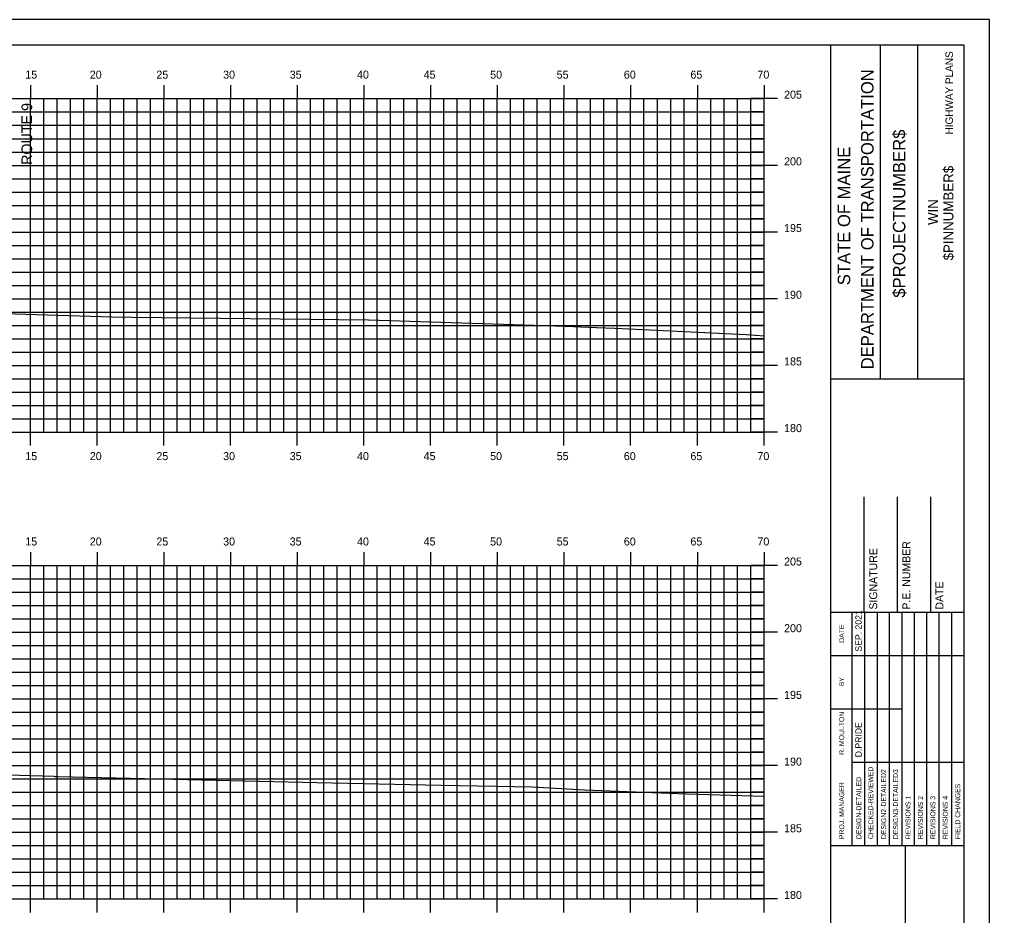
# Model space of a CAD drawing. Extents: x 1723543 to 1723714, y 458501 to 458611.
# Drawn here: x 1723640 to 1723712.7, y 458544 to 458611.2 of the extents above; entities that cross this region are included whole.
import ezdxf

# ---------------------------------------------------------------- set-up
doc = ezdxf.new("R2010")
doc.units = 0
for name, color, linetype in [('ANNOTATION', 7, 'Continuous'), ('BORDER', 7, 'Continuous'), ('H_V ANNOTATION', 7, 'Continuous'), ('HIGHWAY_TITLE', 7, 'Continuous'), ('MAJOR', 7, 'Continuous'), ('MINOR', 7, 'Continuous'), ('PLOT BOUNDARY', 7, 'Continuous'), ('S_Roadway_Centerline', 7, 'Continuous')]:
    doc.layers.add(name, color=color, linetype=linetype)

msp = doc.modelspace()

# ---------------------------------------------------------------- linework, layer by layer
at = {"layer": 'BORDER'}
for p, q in [((1723700.786, 458504.254), (1723700.786, 458609.254)), ((1723704.514, 458584.251), (1723704.514, 458609.251)), ((1723707.309, 458584.251), (1723707.309, 458609.251)), ((1723700.786, 458584.248), (1723710.786, 458584.248)), ((1723703.286, 458566.757), (1723703.286, 458575.405)), ((1723705.786, 458566.757), (1723705.786, 458575.405)), ((1723708.286, 458566.757), (1723708.286, 458575.405)), ((1723700.786, 458566.757), (1723710.786, 458566.757)), ((1723700.786, 458549.257), (1723710.786, 458549.257)), ((1723706.377, 458514.257), (1723706.377, 458549.257))]:
    msp.add_line(p, q, dxfattribs=at)
msp.add_lwpolyline([(1723550.786, 458504.254), (1723710.786, 458504.254), (1723710.786, 458609.254), (1723550.786, 458609.254)], close=True, dxfattribs=at)
for points in [[(1723702.4, 458563.507), (1723702.4, 458566.757)], [(1723703.333, 458549.26), (1723703.333, 458566.757)], [(1723704.265, 458566.757), (1723704.265, 458549.26)], [(1723705.196, 458549.26), (1723705.196, 458566.757)], [(1723706.128, 458549.26), (1723706.128, 458566.757)], [(1723707.06, 458549.26), (1723707.06, 458566.757)], [(1723707.991, 458549.26), (1723707.991, 458566.757)], [(1723708.923, 458549.26), (1723708.923, 458566.757)], [(1723709.855, 458549.26), (1723709.855, 458566.757)], [(1723702.401, 458549.26), (1723702.401, 458566.051)], [(1723700.786, 458563.507), (1723710.786, 458563.507)], [(1723700.786, 458559.507), (1723702.401, 458559.507)], [(1723702.4, 458559.507), (1723706.127, 458559.507)], [(1723702.4, 458555.507), (1723710.786, 458555.507)]]:
    msp.add_lwpolyline(points, dxfattribs=at)
at = {"layer": 'MAJOR'}
for p, q in [((1723640.785, 458606.256), (1723640.785, 458605.254)), ((1723645.785, 458606.256), (1723645.785, 458605.254)), ((1723650.785, 458606.256), (1723650.785, 458605.254)), ((1723655.785, 458606.256), (1723655.785, 458605.254)), ((1723660.785, 458606.256), (1723660.785, 458605.254)), ((1723665.785, 458606.256), (1723665.785, 458605.254)), ((1723670.785, 458606.256), (1723670.785, 458605.254)), ((1723675.785, 458606.256), (1723675.785, 458605.254)), ((1723680.785, 458606.256), (1723680.785, 458605.254)), ((1723685.785, 458606.256), (1723685.785, 458605.254)), ((1723690.785, 458606.256), (1723690.785, 458605.254)), ((1723695.785, 458606.256), (1723695.785, 458605.254)), ((1723555.785, 458605.254), (1723695.785, 458605.254)), ((1723555.785, 458605.254), (1723695.785, 458605.254)), ((1723640.785, 458580.254), (1723640.785, 458605.254)), ((1723645.785, 458580.254), (1723645.785, 458605.254)), ((1723650.785, 458580.254), (1723650.785, 458605.254)), ((1723655.785, 458580.254), (1723655.785, 458605.254)), ((1723660.785, 458580.254), (1723660.785, 458605.254)), ((1723665.785, 458580.254), (1723665.785, 458605.254)), ((1723670.785, 458580.254), (1723670.785, 458605.254)), ((1723675.785, 458580.254), (1723675.785, 458605.254)), ((1723680.785, 458580.254), (1723680.785, 458605.254)), ((1723685.785, 458580.254), (1723685.785, 458605.254)), ((1723690.785, 458580.254), (1723690.785, 458605.254)), ((1723696.787, 458605.254), (1723694.783, 458605.254)), ((1723695.785, 458580.254), (1723695.785, 458605.254)), ((1723695.785, 458580.254), (1723695.785, 458605.254)), ((1723555.785, 458600.254), (1723695.785, 458600.254)), ((1723696.787, 458600.254), (1723694.783, 458600.254)), ((1723555.785, 458595.254), (1723695.785, 458595.254)), ((1723696.787, 458595.254), (1723694.783, 458595.254)), ((1723555.785, 458590.254), (1723695.785, 458590.254)), ((1723696.787, 458590.254), (1723694.783, 458590.254)), ((1723555.785, 458585.254), (1723695.785, 458585.254)), ((1723696.787, 458585.254), (1723694.783, 458585.254)), ((1723555.785, 458580.254), (1723695.785, 458580.254)), ((1723555.785, 458580.254), (1723695.785, 458580.254)), ((1723640.785, 458579.252), (1723640.785, 458580.254)), ((1723645.785, 458579.252), (1723645.785, 458580.254)), ((1723650.785, 458579.252), (1723650.785, 458580.254)), ((1723655.785, 458579.252), (1723655.785, 458580.254)), ((1723660.785, 458579.252), (1723660.785, 458580.254)), ((1723665.785, 458579.252), (1723665.785, 458580.254)), ((1723670.785, 458579.252), (1723670.785, 458580.254)), ((1723675.785, 458579.252), (1723675.785, 458580.254)), ((1723680.785, 458579.252), (1723680.785, 458580.254)), ((1723685.785, 458579.252), (1723685.785, 458580.254)), ((1723690.785, 458579.252), (1723690.785, 458580.254)), ((1723696.787, 458580.254), (1723694.783, 458580.254)), ((1723695.785, 458579.252), (1723695.785, 458580.254)), ((1723640.785, 458571.256), (1723640.785, 458570.254)), ((1723645.785, 458571.256), (1723645.785, 458570.254)), ((1723650.785, 458571.256), (1723650.785, 458570.254)), ((1723655.785, 458571.256), (1723655.785, 458570.254)), ((1723660.785, 458571.256), (1723660.785, 458570.254)), ((1723665.785, 458571.256), (1723665.785, 458570.254)), ((1723670.785, 458571.256), (1723670.785, 458570.254)), ((1723675.785, 458571.256), (1723675.785, 458570.254)), ((1723680.785, 458571.256), (1723680.785, 458570.254)), ((1723685.785, 458571.256), (1723685.785, 458570.254)), ((1723690.785, 458571.256), (1723690.785, 458570.254)), ((1723695.785, 458571.256), (1723695.785, 458570.254)), ((1723555.785, 458570.254), (1723695.785, 458570.254)), ((1723555.785, 458570.254), (1723695.785, 458570.254)), ((1723640.785, 458545.254), (1723640.785, 458570.254)), ((1723645.785, 458545.254), (1723645.785, 458570.254)), ((1723650.785, 458545.254), (1723650.785, 458570.254)), ((1723655.785, 458545.254), (1723655.785, 458570.254)), ((1723660.785, 458545.254), (1723660.785, 458570.254)), ((1723665.785, 458545.254), (1723665.785, 458570.254)), ((1723670.785, 458545.254), (1723670.785, 458570.254)), ((1723675.785, 458545.254), (1723675.785, 458570.254)), ((1723680.785, 458545.254), (1723680.785, 458570.254)), ((1723685.785, 458545.254), (1723685.785, 458570.254)), ((1723690.785, 458545.254), (1723690.785, 458570.254)), ((1723696.787, 458570.254), (1723694.783, 458570.254)), ((1723695.785, 458545.254), (1723695.785, 458570.254)), ((1723695.785, 458545.254), (1723695.785, 458570.254)), ((1723555.785, 458565.254), (1723695.785, 458565.254)), ((1723696.787, 458565.254), (1723694.783, 458565.254)), ((1723555.785, 458560.254), (1723695.785, 458560.254)), ((1723696.787, 458560.254), (1723694.783, 458560.254)), ((1723555.785, 458555.254), (1723695.785, 458555.254)), ((1723696.787, 458555.254), (1723694.783, 458555.254)), ((1723555.785, 458550.254), (1723695.785, 458550.254)), ((1723696.787, 458550.254), (1723694.783, 458550.254)), ((1723555.785, 458545.254), (1723695.785, 458545.254)), ((1723555.785, 458545.254), (1723695.785, 458545.254)), ((1723640.785, 458544.252), (1723640.785, 458545.254)), ((1723645.785, 458544.252), (1723645.785, 458545.254)), ((1723650.785, 458544.252), (1723650.785, 458545.254)), ((1723655.785, 458544.252), (1723655.785, 458545.254)), ((1723660.785, 458544.252), (1723660.785, 458545.254)), ((1723665.785, 458544.252), (1723665.785, 458545.254)), ((1723670.785, 458544.252), (1723670.785, 458545.254)), ((1723675.785, 458544.252), (1723675.785, 458545.254)), ((1723680.785, 458544.252), (1723680.785, 458545.254)), ((1723685.785, 458544.252), (1723685.785, 458545.254)), ((1723690.785, 458544.252), (1723690.785, 458545.254)), ((1723696.787, 458545.254), (1723694.783, 458545.254)), ((1723695.785, 458544.252), (1723695.785, 458545.254))]:
    msp.add_line(p, q, dxfattribs=at)
at = {"layer": 'MINOR'}
for p, q in [((1723641.785, 458580.254), (1723641.785, 458605.254)), ((1723642.785, 458580.254), (1723642.785, 458605.254)), ((1723643.785, 458580.254), (1723643.785, 458605.254)), ((1723644.785, 458580.254), (1723644.785, 458605.254)), ((1723646.785, 458580.254), (1723646.785, 458605.254)), ((1723647.785, 458580.254), (1723647.785, 458605.254)), ((1723648.785, 458580.254), (1723648.785, 458605.254)), ((1723649.785, 458580.254), (1723649.785, 458605.254)), ((1723651.785, 458580.254), (1723651.785, 458605.254)), ((1723652.785, 458580.254), (1723652.785, 458605.254)), ((1723653.785, 458580.254), (1723653.785, 458605.254)), ((1723654.785, 458580.254), (1723654.785, 458605.254)), ((1723656.785, 458580.254), (1723656.785, 458605.254)), ((1723657.785, 458580.254), (1723657.785, 458605.254)), ((1723658.785, 458580.254), (1723658.785, 458605.254)), ((1723659.785, 458580.254), (1723659.785, 458605.254)), ((1723661.785, 458580.254), (1723661.785, 458605.254)), ((1723662.785, 458580.254), (1723662.785, 458605.254)), ((1723663.785, 458580.254), (1723663.785, 458605.254)), ((1723664.785, 458580.254), (1723664.785, 458605.254)), ((1723666.785, 458580.254), (1723666.785, 458605.254)), ((1723667.785, 458580.254), (1723667.785, 458605.254)), ((1723668.785, 458580.254), (1723668.785, 458605.254)), ((1723669.785, 458580.254), (1723669.785, 458605.254)), ((1723671.785, 458580.254), (1723671.785, 458605.254)), ((1723672.785, 458580.254), (1723672.785, 458605.254)), ((1723673.785, 458580.254), (1723673.785, 458605.254)), ((1723674.785, 458580.254), (1723674.785, 458605.254)), ((1723676.785, 458580.254), (1723676.785, 458605.254)), ((1723677.785, 458580.254), (1723677.785, 458605.254)), ((1723678.785, 458580.254), (1723678.785, 458605.254)), ((1723679.785, 458580.254), (1723679.785, 458605.254)), ((1723681.785, 458580.254), (1723681.785, 458605.254)), ((1723682.785, 458580.254), (1723682.785, 458605.254)), ((1723683.785, 458580.254), (1723683.785, 458605.254)), ((1723684.785, 458580.254), (1723684.785, 458605.254)), ((1723686.785, 458580.254), (1723686.785, 458605.254)), ((1723687.785, 458580.254), (1723687.785, 458605.254)), ((1723688.785, 458580.254), (1723688.785, 458605.254)), ((1723689.785, 458580.254), (1723689.785, 458605.254)), ((1723691.785, 458580.254), (1723691.785, 458605.254)), ((1723692.785, 458580.254), (1723692.785, 458605.254)), ((1723693.785, 458580.254), (1723693.785, 458605.254)), ((1723694.785, 458580.254), (1723694.785, 458605.254)), ((1723555.785, 458604.254), (1723695.785, 458604.254)), ((1723695.785, 458604.254), (1723694.783, 458604.254)), ((1723555.785, 458603.254), (1723695.785, 458603.254)), ((1723695.785, 458603.254), (1723694.783, 458603.254)), ((1723555.785, 458602.254), (1723695.785, 458602.254)), ((1723695.785, 458602.254), (1723694.783, 458602.254)), ((1723555.785, 458601.254), (1723695.785, 458601.254)), ((1723695.785, 458601.254), (1723694.783, 458601.254)), ((1723555.785, 458599.254), (1723695.785, 458599.254)), ((1723695.785, 458599.254), (1723694.783, 458599.254)), ((1723555.785, 458598.254), (1723695.785, 458598.254)), ((1723695.785, 458598.254), (1723694.783, 458598.254)), ((1723555.785, 458597.254), (1723695.785, 458597.254)), ((1723695.785, 458597.254), (1723694.783, 458597.254)), ((1723555.785, 458596.254), (1723695.785, 458596.254)), ((1723695.785, 458596.254), (1723694.783, 458596.254)), ((1723555.785, 458594.254), (1723695.785, 458594.254)), ((1723695.785, 458594.254), (1723694.783, 458594.254)), ((1723555.785, 458593.254), (1723695.785, 458593.254)), ((1723695.785, 458593.254), (1723694.783, 458593.254)), ((1723555.785, 458592.254), (1723695.785, 458592.254)), ((1723695.785, 458592.254), (1723694.783, 458592.254)), ((1723555.785, 458591.254), (1723695.785, 458591.254)), ((1723695.785, 458591.254), (1723694.783, 458591.254)), ((1723555.785, 458589.254), (1723695.785, 458589.254)), ((1723695.785, 458589.254), (1723694.783, 458589.254)), ((1723555.785, 458588.254), (1723695.785, 458588.254)), ((1723695.785, 458588.254), (1723694.783, 458588.254)), ((1723555.785, 458587.254), (1723695.785, 458587.254)), ((1723695.785, 458587.254), (1723694.783, 458587.254)), ((1723555.785, 458586.254), (1723695.785, 458586.254)), ((1723695.785, 458586.254), (1723694.783, 458586.254)), ((1723555.785, 458584.254), (1723695.785, 458584.254)), ((1723695.785, 458584.254), (1723694.783, 458584.254)), ((1723555.785, 458583.254), (1723695.785, 458583.254)), ((1723695.785, 458583.254), (1723694.783, 458583.254)), ((1723555.785, 458582.254), (1723695.785, 458582.254)), ((1723695.785, 458582.254), (1723694.783, 458582.254)), ((1723555.785, 458581.254), (1723695.785, 458581.254)), ((1723695.785, 458581.254), (1723694.783, 458581.254)), ((1723641.785, 458545.254), (1723641.785, 458570.254)), ((1723642.785, 458545.254), (1723642.785, 458570.254)), ((1723643.785, 458545.254), (1723643.785, 458570.254)), ((1723644.785, 458545.254), (1723644.785, 458570.254)), ((1723646.785, 458545.254), (1723646.785, 458570.254)), ((1723647.785, 458545.254), (1723647.785, 458570.254)), ((1723648.785, 458545.254), (1723648.785, 458570.254)), ((1723649.785, 458545.254), (1723649.785, 458570.254)), ((1723651.785, 458545.254), (1723651.785, 458570.254)), ((1723652.785, 458545.254), (1723652.785, 458570.254)), ((1723653.785, 458545.254), (1723653.785, 458570.254)), ((1723654.785, 458545.254), (1723654.785, 458570.254)), ((1723656.785, 458545.254), (1723656.785, 458570.254)), ((1723657.785, 458545.254), (1723657.785, 458570.254)), ((1723658.785, 458545.254), (1723658.785, 458570.254)), ((1723659.785, 458545.254), (1723659.785, 458570.254)), ((1723661.785, 458545.254), (1723661.785, 458570.254)), ((1723662.785, 458545.254), (1723662.785, 458570.254)), ((1723663.785, 458545.254), (1723663.785, 458570.254)), ((1723664.785, 458545.254), (1723664.785, 458570.254)), ((1723666.785, 458545.254), (1723666.785, 458570.254)), ((1723667.785, 458545.254), (1723667.785, 458570.254)), ((1723668.785, 458545.254), (1723668.785, 458570.254)), ((1723669.785, 458545.254), (1723669.785, 458570.254)), ((1723671.785, 458545.254), (1723671.785, 458570.254)), ((1723672.785, 458545.254), (1723672.785, 458570.254)), ((1723673.785, 458545.254), (1723673.785, 458570.254)), ((1723674.785, 458545.254), (1723674.785, 458570.254)), ((1723676.785, 458545.254), (1723676.785, 458570.254)), ((1723677.785, 458545.254), (1723677.785, 458570.254)), ((1723678.785, 458545.254), (1723678.785, 458570.254)), ((1723679.785, 458545.254), (1723679.785, 458570.254)), ((1723681.785, 458545.254), (1723681.785, 458570.254)), ((1723682.785, 458545.254), (1723682.785, 458570.254)), ((1723683.785, 458545.254), (1723683.785, 458570.254)), ((1723684.785, 458545.254), (1723684.785, 458570.254)), ((1723686.785, 458545.254), (1723686.785, 458570.254)), ((1723687.785, 458545.254), (1723687.785, 458570.254)), ((1723688.785, 458545.254), (1723688.785, 458570.254)), ((1723689.785, 458545.254), (1723689.785, 458570.254)), ((1723691.785, 458545.254), (1723691.785, 458570.254)), ((1723692.785, 458545.254), (1723692.785, 458570.254)), ((1723693.785, 458545.254), (1723693.785, 458570.254)), ((1723694.785, 458545.254), (1723694.785, 458570.254)), ((1723555.785, 458569.254), (1723695.785, 458569.254)), ((1723695.785, 458569.254), (1723694.783, 458569.254)), ((1723555.785, 458568.254), (1723695.785, 458568.254)), ((1723695.785, 458568.254), (1723694.783, 458568.254)), ((1723555.785, 458567.254), (1723695.785, 458567.254)), ((1723695.785, 458567.254), (1723694.783, 458567.254)), ((1723555.785, 458566.254), (1723695.785, 458566.254)), ((1723695.785, 458566.254), (1723694.783, 458566.254)), ((1723555.785, 458564.254), (1723695.785, 458564.254)), ((1723695.785, 458564.254), (1723694.783, 458564.254)), ((1723555.785, 458563.254), (1723695.785, 458563.254)), ((1723695.785, 458563.254), (1723694.783, 458563.254)), ((1723555.785, 458562.254), (1723695.785, 458562.254)), ((1723695.785, 458562.254), (1723694.783, 458562.254)), ((1723555.785, 458561.254), (1723695.785, 458561.254)), ((1723695.785, 458561.254), (1723694.783, 458561.254)), ((1723555.785, 458559.254), (1723695.785, 458559.254)), ((1723695.785, 458559.254), (1723694.783, 458559.254)), ((1723555.785, 458558.254), (1723695.785, 458558.254)), ((1723695.785, 458558.254), (1723694.783, 458558.254)), ((1723555.785, 458557.254), (1723695.785, 458557.254)), ((1723695.785, 458557.254), (1723694.783, 458557.254)), ((1723555.785, 458556.254), (1723695.785, 458556.254)), ((1723695.785, 458556.254), (1723694.783, 458556.254)), ((1723555.785, 458554.254), (1723695.785, 458554.254)), ((1723695.785, 458554.254), (1723694.783, 458554.254)), ((1723555.785, 458553.254), (1723695.785, 458553.254)), ((1723695.785, 458553.254), (1723694.783, 458553.254)), ((1723555.785, 458552.254), (1723695.785, 458552.254)), ((1723695.785, 458552.254), (1723694.783, 458552.254)), ((1723555.785, 458551.254), (1723695.785, 458551.254)), ((1723695.785, 458551.254), (1723694.783, 458551.254)), ((1723555.785, 458549.254), (1723695.785, 458549.254)), ((1723695.785, 458549.254), (1723694.783, 458549.254)), ((1723555.785, 458548.254), (1723695.785, 458548.254)), ((1723695.785, 458548.254), (1723694.783, 458548.254)), ((1723555.785, 458547.254), (1723695.785, 458547.254)), ((1723695.785, 458547.254), (1723694.783, 458547.254)), ((1723555.785, 458546.254), (1723695.785, 458546.254)), ((1723695.785, 458546.254), (1723694.783, 458546.254))]:
    msp.add_line(p, q, dxfattribs=at)
at = {"layer": 'PLOT BOUNDARY'}
msp.add_lwpolyline([(1723542.692, 458501.195), (1723712.692, 458501.195), (1723712.692, 458611.195), (1723542.692, 458611.195)], close=True, dxfattribs=at)
at = {"layer": 'S_Roadway_Centerline'}
for points in [[(1723555.785, 458591.47), (1723562.634, 458591.225), (1723564.833, 458591.119), (1723566.056, 458591.128), (1723573.85, 458590.931), (1723586.854, 458590.649), (1723589.146, 458590.577), (1723593.094, 458590.494), (1723606.299, 458590.024), (1723622.288, 458589.703), (1723624.211, 458589.684), (1723625.504, 458589.67), (1723636.39, 458589.225), (1723646.889, 458588.895), (1723648.382, 458588.881), (1723666.137, 458588.667), (1723680.866, 458588.185), (1723683.212, 458588.086), (1723684.599, 458588.051), (1723694.44, 458587.568), (1723695.785, 458587.47)], [(1723555.785, 458556.489), (1723564.545, 458556.413), (1723571.514, 458556.395), (1723582.117, 458555.861), (1723583.488, 458555.828), (1723595.581, 458555.866), (1723602.294, 458555.786), (1723607.123, 458555.553), (1723613.878, 458555.293), (1723623.634, 458555.001), (1723642.551, 458554.449), (1723642.611, 458554.446), (1723642.654, 458554.445), (1723642.863, 458554.44), (1723662.248, 458553.975), (1723671.582, 458553.786), (1723678.391, 458553.664), (1723682.357, 458553.433), (1723689.959, 458553.132), (1723695.785, 458552.954)]]:
    msp.add_lwpolyline(points, dxfattribs=at)

# ---------------------------------------------------------------- texts
at = {"layer": 'ANNOTATION'}
msp.add_text('ROUTE 9', height=0.8, rotation=90, dxfattribs=at).set_placement((1723640.918, 458600.288))
at = {"layer": 'BORDER'}
for s, height, p in [('DEPARTMENT OF TRANSPORTATION', 0.93176, (1723703.992, 458584.96)), ('$PROJECTNUMBER$', 0.93176, (1723706.378, 458590.333)), ('STATE OF MAINE', 0.93176, (1723702.241, 458591.266)), ('$PINNUMBER$', 0.74527, (1723709.981, 458593.129)), ('WIN', 0.7453, (1723708.822, 458595.784)), ('SIGNATURE', 0.5906, (1723704.266, 458566.949)), ('P.E. NUMBER', 0.59055, (1723706.746, 458566.949)), ('DATE', 0.5906, (1723709.227, 458566.949)), ('SEP. 2021', 0.4845, (1723703.109, 458563.803)), ('DATE', 0.3714, (1723701.79, 458564.463)), ('BY', 0.3714, (1723701.79, 458561.192)), ('R. MOULTON', 0.3727, (1723701.79, 458556.06)), ('D.PRIDE', 0.4845, (1723703.109, 458555.88)), ('CHECKED-REVIEWED', 0.37275, (1723703.967, 458549.745)), ('DESIGN2-DETAILED2', 0.37275, (1723704.936, 458549.745)), ('DESIGN3-DETAILED3', 0.37275, (1723705.83, 458549.745)), ('DESIGN-DETAILED', 0.37275, (1723703.072, 458549.745)), ('PROJ. MANAGER', 0.37275, (1723701.79, 458549.745)), ('FIELD CHANGES', 0.37275, (1723710.488, 458549.745)), ('REVISIONS 1', 0.37275, (1723706.762, 458549.745)), ('REVISIONS 2', 0.37275, (1723707.693, 458549.745)), ('REVISIONS 3', 0.37275, (1723708.625, 458549.745)), ('REVISIONS 4', 0.37275, (1723709.557, 458549.745))]:
    msp.add_text(s, height=height, rotation=90, dxfattribs=at).set_placement(p)
at = {"layer": 'H_V ANNOTATION'}
for s, p in [('15', (1723640.403, 458606.754)), ('20', (1723645.239, 458606.754)), ('25', (1723650.231, 458606.754)), ('30', (1723655.234, 458606.754)), ('35', (1723660.226, 458606.754)), ('40', (1723665.272, 458606.754)), ('45', (1723670.264, 458606.754)), ('50', (1723675.25, 458606.754)), ('55', (1723680.242, 458606.754)), ('60', (1723685.272, 458606.754)), ('65', (1723690.264, 458606.754)), ('70', (1723695.287, 458606.754)), ('205', (1723697.285, 458605.254)), ('200', (1723697.285, 458600.254)), ('195', (1723697.285, 458595.254)), ('190', (1723697.285, 458590.254)), ('185', (1723697.285, 458585.254)), ('180', (1723697.285, 458580.254)), ('15', (1723640.403, 458578.154)), ('20', (1723645.239, 458578.154)), ('25', (1723650.231, 458578.154)), ('30', (1723655.234, 458578.154)), ('35', (1723660.226, 458578.154)), ('40', (1723665.272, 458578.154)), ('45', (1723670.264, 458578.154)), ('50', (1723675.25, 458578.154)), ('55', (1723680.242, 458578.154)), ('60', (1723685.272, 458578.154)), ('65', (1723690.264, 458578.154)), ('70', (1723695.287, 458578.154)), ('15', (1723640.403, 458571.754)), ('20', (1723645.239, 458571.754)), ('25', (1723650.231, 458571.754)), ('30', (1723655.234, 458571.754)), ('35', (1723660.226, 458571.754)), ('40', (1723665.272, 458571.754)), ('45', (1723670.264, 458571.754)), ('50', (1723675.25, 458571.754)), ('55', (1723680.242, 458571.754)), ('60', (1723685.272, 458571.754)), ('65', (1723690.264, 458571.754)), ('70', (1723695.287, 458571.754)), ('205', (1723697.285, 458570.254)), ('200', (1723697.285, 458565.254)), ('195', (1723697.285, 458560.254)), ('190', (1723697.285, 458555.254)), ('185', (1723697.285, 458550.254)), ('180', (1723697.285, 458545.254))]:
    msp.add_text(s, height=0.6, dxfattribs=at).set_placement(p)
at = {"layer": 'HIGHWAY_TITLE'}
msp.add_text('HIGHWAY PLANS', height=0.55901, rotation=90, dxfattribs=at).set_placement((1723709.944, 458602.57))

doc.saveas('drawing.dxf')
